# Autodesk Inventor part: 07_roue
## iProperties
Shininess: 0.0
Length Units: 11269
Angle Units: 11279
Time Units: 11290
Mass Units: 11283
Length Display Precision: 3
Angle Display Precision: 2
Compacted: True
Created: 2002-11
Part Number: 07_roue
Material: Nylon - 6/6
Document SubType Name: Modélisation
Designer: FIEVET
Density: 1.13
Volumn: 3.945812732303422
Area: 34.931226411746344
PropertySet Name: Model Information
Control State: 0
Master: False
Checked Out: False
Author: FIEVET
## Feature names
1. Révolution1 [Revolution]
2. Extrusion1
3. Extrusion2
4. Réseau circulaire1 [Circular Pattern]
5. Extrusion3
6. Réseau circulaire2 [Circular Pattern]
7. Extrusion4
8. Extrusion5
